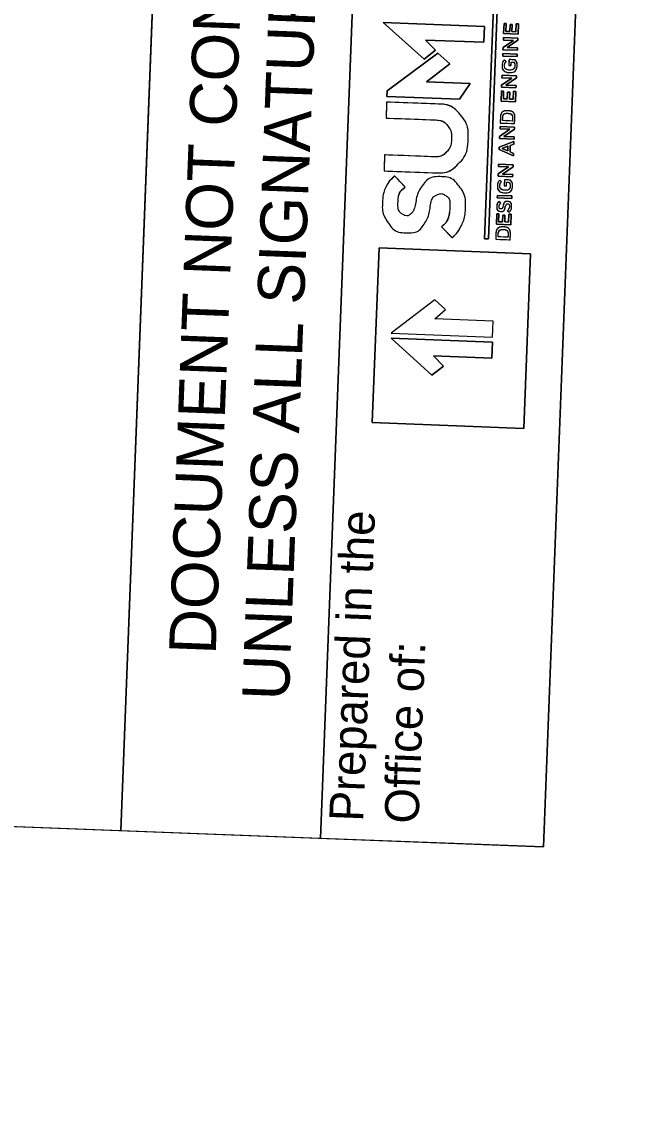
# Model space of a CAD drawing. Extents: x 2097096 to 2098260, y 686401 to 688363.
# Drawn here: x 2097303 to 2097376.9, y 687937.5 to 688066.3 of the extents above; entities that cross this region are included whole.
import ezdxf

# ---------------------------------------------------------------- set-up
doc = ezdxf.new("R2010")
doc.units = 0
for name, color, linetype in [('Sheet Block Title CELL', 7, 'Continuous'), ('Sheet Layout Plan Border', 7, 'Continuous'), ('Sheet Profile CELL', 7, 'Continuous'), ('Sheet Sticker Exception Certification CELL', 7, 'Continuous')]:
    doc.layers.add(name, color=color, linetype=linetype)

msp = doc.modelspace()

# ---------------------------------------------------------------- linework, layer by layer
at = {"layer": 'Sheet Block Title CELL'}
for p, q in [((2097359.93, 688061.68), (2097359.71, 688061.87)), ((2097360.3, 688060.38), (2097360.31, 688060.38)), ((2097360.31, 688060.68), (2097360.31, 688060.68)), ((2097360.13, 688055.89), (2097360.12, 688055.89)), ((2097360.12, 688055.59), (2097360.12, 688055.59)), ((2097348.06, 688046.92), (2097346.81, 688048.22)), ((2097359.39, 688047.54), (2097359.17, 688047.73)), ((2097359.76, 688046.24), (2097359.76, 688046.24)), ((2097359.77, 688046.54), (2097359.77, 688046.54)), ((2097359.28, 688045.05), (2097359.06, 688045.21)), ((2097360.09, 688045.22), (2097360.08, 688045.22)), ((2097360.1, 688044.94), (2097360.1, 688044.94)), ((2097359.28, 688044.34), (2097359.28, 688044.34)), ((2097359.29, 688044.05), (2097359.3, 688044.05)), ((2097360.07, 688044.13), (2097360.27, 688043.95)), ((2097352.32, 688042.25), (2097353.57, 688040.95)), ((2097359.59, 688041.93), (2097359.6, 688041.92)), ((2097359.6, 688042.23), (2097359.6, 688042.23))]:
    msp.add_line(p, q, dxfattribs=at)
for points in [[(2097338.1, 687970.31), (2097345.76, 688170.22), (2097372, 688169.21), (2097364.33, 687969.3)], [(2097344.18, 688019.21), (2097344.97, 688039.76), (2097362.8, 688039.07), (2097362.01, 688018.53)], [(2097346.41, 688029.72), (2097358.33, 688029.26), (2097358.4, 688031.14), (2097351.53, 688031.4), (2097352.8, 688032.52), (2097351.54, 688033.66)]]:
    msp.add_lwpolyline(points, close=True, dxfattribs=at)
for points in [[(2097359.58, 688086.33), (2097357.83, 688040.83), (2097357.38, 688040.84), (2097359.13, 688086.35), (2097359.58, 688086.33)], [(2097359.13, 688086.35), (2097357.38, 688040.84), (2097357.83, 688040.83), (2097359.58, 688086.33), (2097359.13, 688086.35)], [(2097345.46, 688066.28), (2097357.38, 688065.82), (2097357.3, 688063.95), (2097350.43, 688064.21), (2097351.61, 688063), (2097350.27, 688061.96), (2097345.46, 688066.28)], [(2097350.27, 688061.96), (2097351.61, 688063), (2097350.43, 688064.21), (2097357.3, 688063.95), (2097357.38, 688065.82), (2097345.46, 688066.28), (2097350.27, 688061.96)], [(2097359.63, 688064.96), (2097359.67, 688066.16), (2097359.94, 688066.15), (2097359.9, 688065.23), (2097360.35, 688065.21), (2097360.38, 688066.03), (2097360.64, 688066.02), (2097360.61, 688065.2), (2097361.07, 688065.19), (2097361.1, 688066.12), (2097361.37, 688066.11), (2097361.32, 688064.89), (2097359.63, 688064.96)], [(2097361.32, 688064.89), (2097361.37, 688066.11), (2097361.1, 688066.12), (2097361.07, 688065.19), (2097360.61, 688065.2), (2097360.64, 688066.02), (2097360.38, 688066.03), (2097360.35, 688065.21), (2097359.9, 688065.23), (2097359.94, 688066.15), (2097359.67, 688066.16), (2097359.63, 688064.96), (2097361.32, 688064.89)], [(2097359.55, 688063.07), (2097359.56, 688063.34), (2097360.77, 688064.16), (2097359.6, 688064.21), (2097359.61, 688064.49), (2097361.31, 688064.42), (2097361.3, 688064.19), (2097360.05, 688063.33), (2097361.26, 688063.29), (2097361.25, 688063), (2097359.55, 688063.07)], [(2097361.25, 688063), (2097361.26, 688063.29), (2097360.05, 688063.33), (2097361.3, 688064.19), (2097361.31, 688064.42), (2097359.61, 688064.49), (2097359.6, 688064.21), (2097360.77, 688064.16), (2097359.56, 688063.34), (2097359.55, 688063.07), (2097361.25, 688063)], [(2097345.92, 688058.25), (2097351.9, 688062.68), (2097353.31, 688061.4), (2097350.54, 688059.3), (2097355.71, 688059.1), (2097354.43, 688057.26), (2097345.9, 688057.58), (2097345.92, 688058.25)], [(2097345.9, 688057.58), (2097354.43, 688057.26), (2097355.71, 688059.1), (2097350.54, 688059.3), (2097353.31, 688061.4), (2097351.9, 688062.68), (2097345.92, 688058.25), (2097345.9, 688057.58)], [(2097359.52, 688062.33), (2097359.54, 688062.61), (2097361.23, 688062.55), (2097361.22, 688062.26), (2097359.52, 688062.33)], [(2097361.22, 688062.26), (2097361.23, 688062.55), (2097359.54, 688062.61), (2097359.52, 688062.33), (2097361.22, 688062.26)], [(2097360.97, 688061.88), (2097360.26, 688061.91), (2097360.23, 688061.21), (2097360.49, 688061.2), (2097360.51, 688061.62), (2097360.83, 688061.61)], [(2097359.38, 688058.65), (2097359.39, 688058.91), (2097360.6, 688059.74), (2097359.43, 688059.78), (2097359.44, 688060.07), (2097361.14, 688060), (2097361.13, 688059.76), (2097359.88, 688058.91), (2097361.09, 688058.86), (2097361.08, 688058.58), (2097359.38, 688058.65)], [(2097361.08, 688058.58), (2097361.09, 688058.86), (2097359.88, 688058.91), (2097361.13, 688059.76), (2097361.14, 688060), (2097359.44, 688060.07), (2097359.43, 688059.78), (2097360.6, 688059.74), (2097359.39, 688058.91), (2097359.38, 688058.65), (2097361.08, 688058.58)], [(2097359.32, 688057.02), (2097359.37, 688058.22), (2097359.63, 688058.21), (2097359.6, 688057.29), (2097360.04, 688057.28), (2097360.07, 688058.09), (2097360.34, 688058.08), (2097360.31, 688057.27), (2097360.76, 688057.25), (2097360.8, 688058.18), (2097361.07, 688058.17), (2097361.02, 688056.95), (2097359.32, 688057.02)], [(2097361.02, 688056.95), (2097361.07, 688058.17), (2097360.8, 688058.18), (2097360.76, 688057.25), (2097360.31, 688057.27), (2097360.34, 688058.08), (2097360.07, 688058.09), (2097360.04, 688057.28), (2097359.6, 688057.29), (2097359.63, 688058.21), (2097359.37, 688058.22), (2097359.32, 688057.02), (2097361.02, 688056.95)], [(2097352.02, 688056.67), (2097345.87, 688056.91), (2097345.8, 688055.03), (2097351.43, 688054.82)], [(2097359.25, 688055.06), (2097359.22, 688054.45), (2097360.92, 688054.39), (2097360.94, 688054.99)], [(2097360.67, 688055.01), (2097360.66, 688054.68), (2097359.51, 688054.73), (2097359.52, 688055.05)], [(2097359.15, 688052.61), (2097359.16, 688052.88), (2097360.37, 688053.71), (2097359.2, 688053.75), (2097359.21, 688054.03), (2097360.91, 688053.97), (2097360.9, 688053.73), (2097359.65, 688052.88), (2097360.86, 688052.83), (2097360.85, 688052.55), (2097359.15, 688052.61)], [(2097360.85, 688052.55), (2097360.86, 688052.83), (2097359.65, 688052.88), (2097360.9, 688053.73), (2097360.91, 688053.97), (2097359.21, 688054.03), (2097359.2, 688053.75), (2097360.37, 688053.71), (2097359.16, 688052.88), (2097359.15, 688052.61), (2097360.85, 688052.55)], [(2097359.09, 688051.35), (2097359.1, 688051.62), (2097360.84, 688052.27), (2097360.83, 688051.97), (2097360.41, 688051.82), (2097360.38, 688051.05), (2097360.79, 688050.86), (2097360.78, 688050.57), (2097359.09, 688051.35)], [(2097360.78, 688050.57), (2097360.79, 688050.86), (2097360.38, 688051.05), (2097360.41, 688051.82), (2097360.83, 688051.97), (2097360.84, 688052.27), (2097359.1, 688051.62), (2097359.09, 688051.35), (2097360.78, 688050.57)], [(2097360.14, 688051.72), (2097359.45, 688051.47), (2097360.12, 688051.16), (2097360.14, 688051.72)], [(2097360.12, 688051.16), (2097359.45, 688051.47), (2097360.14, 688051.72), (2097360.12, 688051.16)], [(2097351.26, 688050.48), (2097345.63, 688050.7), (2097345.56, 688048.82), (2097351.71, 688048.58)], [(2097358.98, 688048.19), (2097358.99, 688048.46), (2097360.2, 688049.29), (2097359.03, 688049.33), (2097359.04, 688049.61), (2097360.74, 688049.55), (2097360.73, 688049.31), (2097359.48, 688048.45), (2097360.69, 688048.41), (2097360.68, 688048.13), (2097358.98, 688048.19)], [(2097360.68, 688048.13), (2097360.69, 688048.41), (2097359.48, 688048.45), (2097360.73, 688049.31), (2097360.74, 688049.55), (2097359.04, 688049.61), (2097359.03, 688049.33), (2097360.2, 688049.29), (2097358.99, 688048.46), (2097358.98, 688048.19), (2097360.68, 688048.13)], [(2097360.43, 688047.74), (2097359.72, 688047.77), (2097359.69, 688047.07), (2097359.95, 688047.06), (2097359.97, 688047.48), (2097360.28, 688047.47)], [(2097358.88, 688045.65), (2097358.9, 688045.93), (2097360.59, 688045.87), (2097360.58, 688045.58), (2097358.88, 688045.65)], [(2097360.58, 688045.58), (2097360.59, 688045.87), (2097358.9, 688045.93), (2097358.88, 688045.65), (2097360.58, 688045.58)], [(2097358.77, 688042.56), (2097358.81, 688043.77), (2097359.08, 688043.76), (2097359.04, 688042.83), (2097359.49, 688042.82), (2097359.52, 688043.63), (2097359.78, 688043.62), (2097359.75, 688042.81), (2097360.21, 688042.79), (2097360.25, 688043.72), (2097360.51, 688043.71), (2097360.47, 688042.49), (2097358.77, 688042.56)], [(2097360.47, 688042.49), (2097360.51, 688043.71), (2097360.25, 688043.72), (2097360.21, 688042.79), (2097359.75, 688042.81), (2097359.78, 688043.62), (2097359.52, 688043.63), (2097359.49, 688042.82), (2097359.04, 688042.83), (2097359.08, 688043.76), (2097358.81, 688043.77), (2097358.77, 688042.56), (2097360.47, 688042.49)], [(2097358.72, 688041.39), (2097358.7, 688040.78), (2097360.4, 688040.72), (2097360.42, 688041.33)], [(2097360.15, 688041.34), (2097360.14, 688041.02), (2097358.98, 688041.06), (2097358.99, 688041.38)], [(2097344.97, 688039.76), (2097344.18, 688019.21), (2097362.01, 688018.53), (2097362.8, 688039.07), (2097344.97, 688039.76)], [(2097346.41, 688029.72), (2097358.33, 688029.26), (2097358.4, 688031.14), (2097351.53, 688031.4), (2097352.8, 688032.52), (2097351.54, 688033.66), (2097346.41, 688029.72)], [(2097346.39, 688029.14), (2097358.31, 688028.68), (2097358.24, 688026.8), (2097351.36, 688027.07), (2097352.55, 688025.86), (2097351.2, 688024.81), (2097346.39, 688029.14)], [(2097351.2, 688024.81), (2097352.55, 688025.86), (2097351.36, 688027.07), (2097358.24, 688026.8), (2097358.31, 688028.68), (2097346.39, 688029.14), (2097351.2, 688024.81)]]:
    msp.add_lwpolyline(points, dxfattribs=at)
for points, degree in [([(2097360.31, 688060.38), (2097360.31, 688060.38), (2097360.3, 688060.38), (2097360.3, 688060.38), (2097359.83, 688060.4), (2097359.44, 688060.76), (2097359.45, 688061.25), (2097359.47, 688061.54), (2097359.55, 688061.71), (2097359.71, 688061.87), (2097359.71, 688061.87), (2097359.93, 688061.68), (2097359.93, 688061.68), (2097359.81, 688061.56), (2097359.74, 688061.44), (2097359.73, 688061.23), (2097359.72, 688060.93), (2097359.98, 688060.69), (2097360.31, 688060.68), (2097360.31, 688060.68), (2097360.31, 688060.68), (2097360.31, 688060.68), (2097360.66, 688060.67), (2097360.93, 688060.88), (2097360.94, 688061.21), (2097360.95, 688061.36), (2097360.9, 688061.51), (2097360.83, 688061.61), (2097360.83, 688061.61), (2097360.51, 688061.62), (2097360.51, 688061.62), (2097360.51, 688061.62), (2097360.49, 688061.2), (2097360.49, 688061.2), (2097360.49, 688061.2), (2097360.23, 688061.21), (2097360.23, 688061.21), (2097360.23, 688061.21), (2097360.26, 688061.91), (2097360.26, 688061.91), (2097360.26, 688061.91), (2097360.97, 688061.88), (2097360.97, 688061.88), (2097361.11, 688061.72), (2097361.22, 688061.48), (2097361.21, 688061.19), (2097361.19, 688060.68), (2097360.8, 688060.36), (2097360.31, 688060.38)], 3), ([(2097359.71, 688061.87), (2097359.55, 688061.71), (2097359.47, 688061.54), (2097359.45, 688061.25), (2097359.44, 688060.76), (2097359.83, 688060.4), (2097360.3, 688060.38)], 3), ([(2097360.31, 688060.68), (2097359.98, 688060.69), (2097359.72, 688060.93), (2097359.73, 688061.23), (2097359.74, 688061.44), (2097359.81, 688061.56), (2097359.93, 688061.68)], 3), ([(2097360.31, 688060.38), (2097360.8, 688060.36), (2097361.19, 688060.68), (2097361.21, 688061.19), (2097361.22, 688061.48), (2097361.11, 688061.72), (2097360.97, 688061.88)], 3), ([(2097360.83, 688061.61), (2097360.9, 688061.51), (2097360.95, 688061.36), (2097360.94, 688061.21), (2097360.93, 688060.88), (2097360.66, 688060.67), (2097360.31, 688060.68)], 3), ([(2097345.63, 688050.7), (2097345.63, 688050.7), (2097351.26, 688050.48), (2097351.26, 688050.48), (2097352, 688050.45), (2097352.55, 688050.65), (2097352.92, 688051.05), (2097353.28, 688051.45), (2097353.47, 688051.97), (2097353.5, 688052.59), (2097353.52, 688053.22), (2097353.37, 688053.72), (2097353.03, 688054.15), (2097352.7, 688054.58), (2097352.17, 688054.79), (2097351.43, 688054.82), (2097351.43, 688054.82), (2097345.8, 688055.03), (2097345.8, 688055.03), (2097345.8, 688055.03), (2097345.87, 688056.91), (2097345.87, 688056.91), (2097345.87, 688056.91), (2097352.02, 688056.67), (2097352.02, 688056.67), (2097353.02, 688056.64), (2097353.85, 688056.24), (2097354.52, 688055.44), (2097355.18, 688054.65), (2097355.5, 688053.68), (2097355.45, 688052.51), (2097355.41, 688051.34), (2097355.02, 688050.39), (2097354.3, 688049.64), (2097353.57, 688048.9), (2097352.71, 688048.55), (2097351.71, 688048.58), (2097351.71, 688048.58), (2097345.56, 688048.82), (2097345.56, 688048.82), (2097345.56, 688048.82), (2097345.63, 688050.7), (2097345.63, 688050.7)], 3), ([(2097351.71, 688048.58), (2097352.71, 688048.55), (2097353.57, 688048.9), (2097354.3, 688049.64), (2097355.02, 688050.39), (2097355.41, 688051.34), (2097355.45, 688052.51), (2097355.5, 688053.68), (2097355.18, 688054.65), (2097354.52, 688055.44), (2097353.85, 688056.24), (2097353.02, 688056.64), (2097352.02, 688056.67)], 3), ([(2097351.43, 688054.82), (2097352.17, 688054.79), (2097352.7, 688054.58), (2097353.03, 688054.15), (2097353.37, 688053.72), (2097353.52, 688053.22), (2097353.5, 688052.59), (2097353.47, 688051.97), (2097353.28, 688051.45), (2097352.92, 688051.05), (2097352.55, 688050.65), (2097352, 688050.45), (2097351.26, 688050.48)], 3), ([(2097359.22, 688054.45), (2097359.22, 688054.45), (2097359.25, 688055.06), (2097359.25, 688055.06), (2097359.27, 688055.57), (2097359.65, 688055.91), (2097360.12, 688055.89), (2097360.12, 688055.89), (2097360.13, 688055.89), (2097360.13, 688055.89), (2097360.61, 688055.87), (2097360.96, 688055.51), (2097360.94, 688054.99), (2097360.94, 688054.99), (2097360.92, 688054.39), (2097360.92, 688054.39), (2097360.92, 688054.39), (2097359.22, 688054.45), (2097359.22, 688054.45)], 3), ([(2097360.12, 688055.89), (2097359.65, 688055.91), (2097359.27, 688055.57), (2097359.25, 688055.06)], 2), ([(2097359.51, 688054.73), (2097359.51, 688054.73), (2097360.66, 688054.68), (2097360.66, 688054.68), (2097360.66, 688054.68), (2097360.67, 688055.01), (2097360.67, 688055.01), (2097360.69, 688055.35), (2097360.45, 688055.58), (2097360.12, 688055.59), (2097360.12, 688055.59), (2097360.12, 688055.59), (2097360.12, 688055.59), (2097359.78, 688055.61), (2097359.53, 688055.39), (2097359.52, 688055.05), (2097359.52, 688055.05), (2097359.51, 688054.73), (2097359.51, 688054.73)], 3), ([(2097359.52, 688055.05), (2097359.53, 688055.39), (2097359.78, 688055.61), (2097360.12, 688055.59)], 2), ([(2097360.12, 688055.59), (2097360.45, 688055.58), (2097360.69, 688055.35), (2097360.67, 688055.01)], 2), ([(2097360.94, 688054.99), (2097360.96, 688055.51), (2097360.61, 688055.87), (2097360.13, 688055.89)], 2), ([(2097345.78, 688046.91), (2097346.01, 688047.39), (2097346.35, 688047.82), (2097346.81, 688048.22), (2097346.81, 688048.22), (2097348.06, 688046.92), (2097348.06, 688046.92), (2097347.52, 688046.52), (2097347.24, 688045.95), (2097347.21, 688045.2), (2097347.18, 688044.45), (2097347.35, 688043.97), (2097347.71, 688043.74), (2097348.07, 688043.52), (2097348.39, 688043.51), (2097348.65, 688043.71), (2097348.92, 688043.91), (2097349.14, 688044.38), (2097349.3, 688045.12), (2097349.41, 688045.91), (2097349.71, 688046.62), (2097350.19, 688047.25), (2097350.67, 688047.87), (2097351.41, 688048.17), (2097352.41, 688048.13), (2097353.19, 688048.1), (2097353.85, 688047.73), (2097354.39, 688047.02), (2097354.93, 688046.31), (2097355.18, 688045.49), (2097355.15, 688044.58), (2097355.11, 688043.71), (2097354.95, 688042.99), (2097354.67, 688042.41), (2097354.39, 688041.84), (2097354.02, 688041.35), (2097353.57, 688040.95), (2097353.57, 688040.95), (2097352.32, 688042.25), (2097352.32, 688042.25), (2097352.85, 688042.65), (2097353.19, 688043.35), (2097353.31, 688044.34), (2097353.34, 688045.18), (2097353.18, 688045.7), (2097352.82, 688045.92), (2097352.46, 688046.14), (2097352.09, 688046.16), (2097351.71, 688045.96), (2097351.33, 688045.77), (2097351.08, 688045.26), (2097350.97, 688044.43), (2097350.85, 688043.69), (2097350.58, 688043.01), (2097350.17, 688042.4), (2097349.75, 688041.79), (2097349.07, 688041.5), (2097348.11, 688041.54), (2097347.25, 688041.57), (2097346.57, 688041.95), (2097346.07, 688042.68), (2097345.58, 688043.41), (2097345.34, 688044.15), (2097345.37, 688044.9), (2097345.41, 688045.77), (2097345.54, 688046.44), (2097345.78, 688046.91)], 3), ([(2097346.81, 688048.22), (2097346.35, 688047.82), (2097346.01, 688047.39), (2097345.78, 688046.91)], 2), ([(2097353.57, 688040.95), (2097354.02, 688041.35), (2097354.39, 688041.84), (2097354.67, 688042.41), (2097354.95, 688042.99), (2097355.11, 688043.71), (2097355.15, 688044.58), (2097355.18, 688045.49), (2097354.93, 688046.31), (2097354.39, 688047.02), (2097353.85, 688047.73), (2097353.19, 688048.1), (2097352.41, 688048.13), (2097351.41, 688048.17), (2097350.67, 688047.87), (2097350.19, 688047.25), (2097349.71, 688046.62), (2097349.41, 688045.91), (2097349.3, 688045.12), (2097349.14, 688044.38), (2097348.92, 688043.91), (2097348.65, 688043.71), (2097348.39, 688043.51), (2097348.07, 688043.52), (2097347.71, 688043.74), (2097347.35, 688043.97), (2097347.18, 688044.45), (2097347.21, 688045.2), (2097347.24, 688045.95), (2097347.52, 688046.52), (2097348.06, 688046.92)], 3), ([(2097359.76, 688046.24), (2097359.76, 688046.24), (2097359.76, 688046.24), (2097359.76, 688046.24), (2097359.28, 688046.26), (2097358.89, 688046.62), (2097358.91, 688047.11), (2097358.92, 688047.4), (2097359.01, 688047.57), (2097359.17, 688047.73), (2097359.17, 688047.73), (2097359.39, 688047.54), (2097359.39, 688047.54), (2097359.27, 688047.42), (2097359.19, 688047.3), (2097359.19, 688047.09), (2097359.17, 688046.79), (2097359.44, 688046.55), (2097359.77, 688046.54), (2097359.77, 688046.54), (2097359.77, 688046.54), (2097359.77, 688046.54), (2097360.12, 688046.53), (2097360.39, 688046.74), (2097360.4, 688047.07), (2097360.4, 688047.22), (2097360.36, 688047.37), (2097360.28, 688047.47), (2097360.28, 688047.47), (2097359.97, 688047.48), (2097359.97, 688047.48), (2097359.97, 688047.48), (2097359.95, 688047.06), (2097359.95, 688047.06), (2097359.95, 688047.06), (2097359.69, 688047.07), (2097359.69, 688047.07), (2097359.69, 688047.07), (2097359.72, 688047.77), (2097359.72, 688047.77), (2097359.72, 688047.77), (2097360.43, 688047.74), (2097360.43, 688047.74), (2097360.57, 688047.57), (2097360.68, 688047.34), (2097360.67, 688047.05), (2097360.65, 688046.54), (2097360.26, 688046.22), (2097359.76, 688046.24)], 3), ([(2097359.17, 688047.73), (2097359.01, 688047.57), (2097358.92, 688047.4), (2097358.91, 688047.11), (2097358.89, 688046.62), (2097359.28, 688046.26), (2097359.76, 688046.24)], 3), ([(2097359.77, 688046.54), (2097359.44, 688046.55), (2097359.17, 688046.79), (2097359.19, 688047.09), (2097359.19, 688047.3), (2097359.27, 688047.42), (2097359.39, 688047.54)], 3), ([(2097359.76, 688046.24), (2097360.26, 688046.22), (2097360.65, 688046.54), (2097360.67, 688047.05), (2097360.68, 688047.34), (2097360.57, 688047.57), (2097360.43, 688047.74)], 3), ([(2097360.28, 688047.47), (2097360.36, 688047.37), (2097360.4, 688047.22), (2097360.4, 688047.07), (2097360.39, 688046.74), (2097360.12, 688046.53), (2097359.77, 688046.54)], 3), ([(2097345.78, 688046.91), (2097345.54, 688046.44), (2097345.41, 688045.77), (2097345.37, 688044.9), (2097345.34, 688044.15), (2097345.58, 688043.41), (2097346.07, 688042.68), (2097346.57, 688041.95), (2097347.25, 688041.57), (2097348.11, 688041.54), (2097349.07, 688041.5), (2097349.75, 688041.79), (2097350.17, 688042.4), (2097350.58, 688043.01), (2097350.85, 688043.69), (2097350.97, 688044.43), (2097351.08, 688045.26), (2097351.33, 688045.77), (2097351.71, 688045.96), (2097352.09, 688046.16), (2097352.46, 688046.14), (2097352.82, 688045.92), (2097353.18, 688045.7), (2097353.34, 688045.18), (2097353.31, 688044.34), (2097353.19, 688043.35), (2097352.85, 688042.65), (2097352.32, 688042.25)], 3), ([(2097360.27, 688043.95), (2097360.27, 688043.95), (2097360.07, 688044.13), (2097360.07, 688044.13), (2097360.21, 688044.28), (2097360.3, 688044.44), (2097360.31, 688044.64), (2097360.31, 688044.82), (2097360.23, 688044.93), (2097360.1, 688044.94), (2097360.1, 688044.94), (2097360.1, 688044.94), (2097360.1, 688044.94), (2097359.98, 688044.94), (2097359.91, 688044.88), (2097359.83, 688044.58), (2097359.73, 688044.23), (2097359.61, 688044.04), (2097359.3, 688044.05), (2097359.3, 688044.05), (2097359.29, 688044.05), (2097359.29, 688044.05), (2097359, 688044.07), (2097358.81, 688044.31), (2097358.82, 688044.63), (2097358.83, 688044.87), (2097358.91, 688045.05), (2097359.06, 688045.21), (2097359.06, 688045.21), (2097359.28, 688045.05), (2097359.28, 688045.05), (2097359.16, 688044.91), (2097359.09, 688044.76), (2097359.09, 688044.62), (2097359.08, 688044.45), (2097359.17, 688044.35), (2097359.28, 688044.34), (2097359.28, 688044.34), (2097359.28, 688044.34), (2097359.28, 688044.34), (2097359.41, 688044.34), (2097359.47, 688044.41), (2097359.56, 688044.72), (2097359.66, 688045.06), (2097359.8, 688045.23), (2097360.08, 688045.22), (2097360.08, 688045.22), (2097360.09, 688045.22), (2097360.09, 688045.22), (2097360.4, 688045.21), (2097360.58, 688044.96), (2097360.57, 688044.62), (2097360.56, 688044.37), (2097360.46, 688044.14), (2097360.27, 688043.95)], 3), ([(2097359.06, 688045.21), (2097358.91, 688045.05), (2097358.83, 688044.87), (2097358.82, 688044.63), (2097358.81, 688044.31), (2097359, 688044.07), (2097359.29, 688044.05)], 3), ([(2097359.28, 688044.34), (2097359.17, 688044.35), (2097359.08, 688044.45), (2097359.09, 688044.62), (2097359.09, 688044.76), (2097359.16, 688044.91), (2097359.28, 688045.05)], 3), ([(2097360.08, 688045.22), (2097359.8, 688045.23), (2097359.66, 688045.06), (2097359.56, 688044.72), (2097359.47, 688044.41), (2097359.41, 688044.34), (2097359.28, 688044.34)], 3), ([(2097359.3, 688044.05), (2097359.61, 688044.04), (2097359.73, 688044.23), (2097359.83, 688044.58), (2097359.91, 688044.88), (2097359.98, 688044.94), (2097360.1, 688044.94)], 3), ([(2097360.1, 688044.94), (2097360.23, 688044.93), (2097360.31, 688044.82), (2097360.31, 688044.64), (2097360.3, 688044.44), (2097360.21, 688044.28), (2097360.07, 688044.13)], 3), ([(2097360.27, 688043.95), (2097360.46, 688044.14), (2097360.56, 688044.37), (2097360.57, 688044.62), (2097360.58, 688044.96), (2097360.4, 688045.21), (2097360.09, 688045.22)], 3), ([(2097358.7, 688040.78), (2097358.7, 688040.78), (2097358.72, 688041.39), (2097358.72, 688041.39), (2097358.74, 688041.9), (2097359.12, 688042.24), (2097359.6, 688042.23), (2097359.6, 688042.23), (2097359.6, 688042.23), (2097359.6, 688042.23), (2097360.08, 688042.21), (2097360.44, 688041.84), (2097360.42, 688041.33), (2097360.42, 688041.33), (2097360.4, 688040.72), (2097360.4, 688040.72), (2097360.4, 688040.72), (2097358.7, 688040.78), (2097358.7, 688040.78)], 3), ([(2097359.6, 688042.23), (2097359.12, 688042.24), (2097358.74, 688041.9), (2097358.72, 688041.39)], 2), ([(2097358.98, 688041.06), (2097358.98, 688041.06), (2097360.14, 688041.02), (2097360.14, 688041.02), (2097360.14, 688041.02), (2097360.15, 688041.34), (2097360.15, 688041.34), (2097360.16, 688041.68), (2097359.93, 688041.91), (2097359.6, 688041.92), (2097359.6, 688041.92), (2097359.59, 688041.93), (2097359.59, 688041.93), (2097359.26, 688041.94), (2097359.01, 688041.72), (2097358.99, 688041.38), (2097358.99, 688041.38), (2097358.98, 688041.06), (2097358.98, 688041.06)], 3), ([(2097358.99, 688041.38), (2097359.01, 688041.72), (2097359.26, 688041.94), (2097359.59, 688041.93)], 2), ([(2097360.42, 688041.33), (2097360.44, 688041.84), (2097360.08, 688042.21), (2097359.6, 688042.23)], 2), ([(2097359.6, 688041.92), (2097359.93, 688041.91), (2097360.16, 688041.68), (2097360.15, 688041.34)], 2)]:
    msp.add_open_spline(points, degree=degree, dxfattribs=at)
at = {"layer": 'Sheet Layout Plan Border'}
msp.add_lwpolyline([(2098179.19, 686705.44), (2097129.59, 686735.95), (2097177.17, 687976.48), (2097364.33, 687969.3), (2097368.7, 688083.22), (2098230.76, 688050.16)], close=True, dxfattribs=at)
at = {"layer": 'Sheet Profile CELL'}
msp.add_lwpolyline([(2097202.2, 687975.52), (2097206.03, 688075.5), (2097318.45, 688071.19), (2097314.61, 687971.21)], close=True, dxfattribs=at)
at = {"layer": 'Sheet Sticker Exception Certification CELL'}
for p, q in [((2097314.61, 687971.21), (2097322.28, 688171.1)), ((2097345.76, 688170.2), (2097338.1, 687970.31)), ((2097338.1, 687970.31), (2097314.61, 687971.21))]:
    msp.add_line(p, q, dxfattribs=at)

# ---------------------------------------------------------------- texts
at = {"layer": 'Sheet Block Title CELL'}
for s, height, p in [('Prepared in the ', 4.0012, (2097343.11, 687972.24)), ('Office of:', 4.001, (2097349.61, 687971.99))]:
    msp.add_text(s, height=height, rotation=87.8037, dxfattribs=at).set_placement(p)
at = {"layer": 'Sheet Sticker Exception Certification CELL'}
for s, p in [('UNLESS ALL SIGNATURES COMPLETED', (2097334.36, 687986.46)), ('DOCUMENT NOT CONSIDERED FINAL', (2097325.76, 687991.87))]:
    msp.add_text(s, height=5.5, rotation=87.8037, dxfattribs=at).set_placement(p)

doc.saveas('drawing.dxf')
